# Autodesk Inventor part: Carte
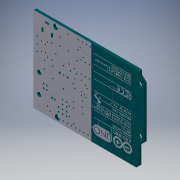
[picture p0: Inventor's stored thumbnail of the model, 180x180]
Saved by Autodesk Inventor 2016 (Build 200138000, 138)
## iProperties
Created: 2018-03
Part Number: Carte
Material: Générique
Document SubType Name: Modeling
Designer: Bruno
Density: 1 g/cm^3
Appearance: Par défaut
Author: Bruno
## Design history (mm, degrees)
feature "Composite1"
body "Srf1"
